// Mitsubishi GX Works2 project: MC-34MR-4MTS-F700-FX-A-220V例程   PLC: FX1S

PROGRAM MAIN
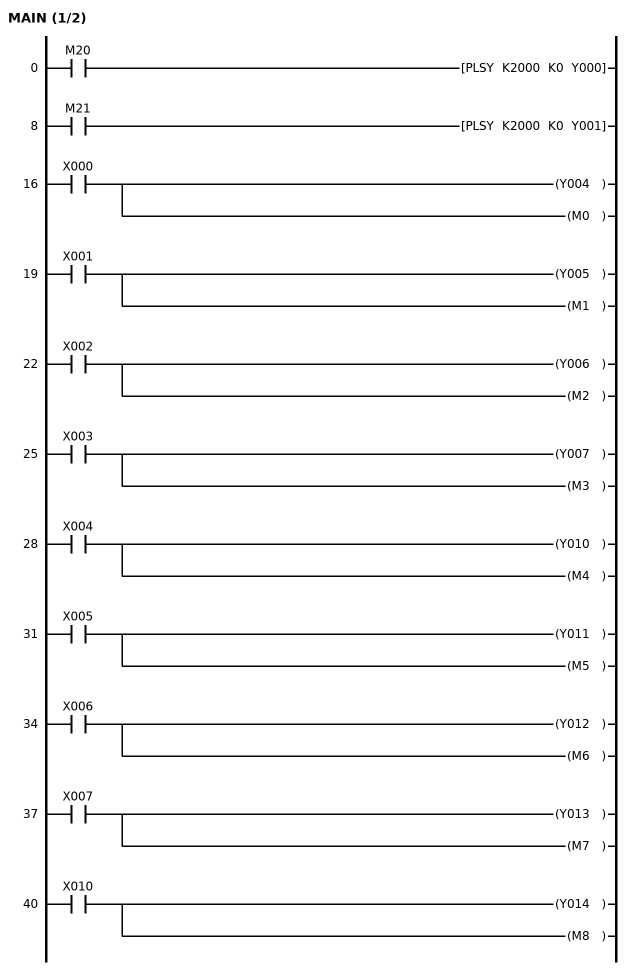
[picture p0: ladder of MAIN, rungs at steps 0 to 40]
0     LD      M20
      PLSY    K2000 K0 Y000
8     LD      M21
      PLSY    K2000 K0 Y001
16    LD      X000
      OUT     Y004
      OUT     M0
19    LD      X001
      OUT     Y005
      OUT     M1
22    LD      X002
      OUT     Y006
      OUT     M2
25    LD      X003
      OUT     Y007
      OUT     M3
28    LD      X004
      OUT     Y010
      OUT     M4
31    LD      X005
      OUT     Y011
      OUT     M5
34    LD      X006
      OUT     Y012
      OUT     M6
37    LD      X007
      OUT     Y013
      OUT     M7
40    LD      X010
      OUT     Y014
      OUT     M8
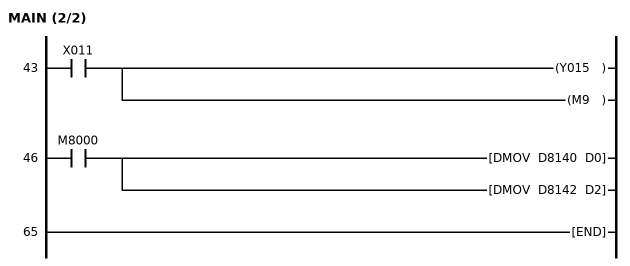
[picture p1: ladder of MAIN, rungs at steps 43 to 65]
43    LD      X011
      OUT     Y015
      OUT     M9
46    LD      M8000
      DMOV    D8140 D0
      DMOV    D8142 D2
65    END
END_PROGRAM
